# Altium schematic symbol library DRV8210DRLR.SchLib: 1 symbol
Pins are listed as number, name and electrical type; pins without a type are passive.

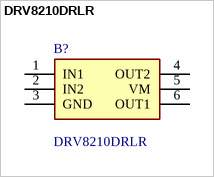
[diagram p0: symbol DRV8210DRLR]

## DRV8210DRLR
designator B?
Motor / Motion / Ignition Controllers & Drivers 12-V, 1.76-A brushed DC motor driver with auto sleep mode; Manufacturer_Name: Texas Instruments; Geometry.Height: 0.6mm
footprint SOTFL50P160X60-6N
pins: 1 IN1, 2 IN2, 3 GND, 4 OUT2, 5 VM, 6 OUT1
